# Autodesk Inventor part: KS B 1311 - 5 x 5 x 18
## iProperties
Created: 2009-02
Part Number: KS B 1311 - 5 x 5 x 18
Material: 강, 연강
Description: 키 및 해당 키홈
Document SubType Name: Modeling
Standard: KS B 1311
Designer: KYOUNG IL JANG
Standards Organization: KS
Language: ko-KR
Size Designation: 5 x 5 x 18
Categories: <MemberInstance><Categories><Category DisplayName="샤프트 부품" InternalName="7f7aeb1f-a693-4053-b835-cee3144e0d98" Mnemonic="SHFT"><Category DisplayName="키" Interna
Density: 1 g/cm^3
IsCustomPart: 0
Author: KYOUNG IL JANG
